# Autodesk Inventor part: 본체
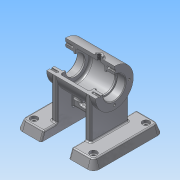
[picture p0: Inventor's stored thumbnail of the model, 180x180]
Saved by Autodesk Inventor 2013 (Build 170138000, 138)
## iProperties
Created: 2016-07
Part Number: 본체
Material: 알루미늄 6061
Document SubType Name: Modeling
Designer: Administrator
Density: 2.71 g/cm^3
Mass: 499.755 g
Surface Area: 541.889 cm^2
Volume: 184.411 cm^3
Author: Administrator
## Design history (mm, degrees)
sketch "스케치1"
  geometry: L1 (0, 0)-(0, 70); L2 (0, 70)-(70, 70); L3 (0, 87)-(0, 97); L4 (0, 97)-(70, 97); L5 (70, 97)-(70, 87); L6 (1, 86)-(11.7, 86); L7 (12, 85.7)-(12, 84); L8 (12, 84)-(14, 84); L9 (14, 84)-(14, 89); L10 (17, 92)-(53, 92); L11 (56, 89)-(56, 84); L12 (56, 84)-(58, 84); L13 (58, 84)-(58, 85.7); L14 (58.3, 86)-(69, 86); L15 (69, 86)-(70, 87); L16 (1, 86)-(0, 87); A1 r 0.3 centre (11.7, 85.7) between (12, 85.7) and (11.7, 86); A2 r 0.3 centre (58.3, 85.7) between (58.3, 86) and (58, 85.7); A3 r 3 centre (53, 89) between (56, 89) and (53, 92); A4 r 3 centre (17, 89) between (17, 92) and (14, 89); 7 further points
  constraints: 32 end point, 16 point on line, 8 point on circle, 8 tangent, 7 perpendicular, 6 parallel, 4 centre point, 2 equal radius, 1 vertical
  dimensions: "d0" = 70 distance of L1.start L1.end; "d1" = 70 distance of L1.end L2.end; "d2" = 54 diameter of L4 L2; "d3" = 12 distance of point (0, 86) point (12, 86); "d4" = 2 distance of L7.end L8.end; "d5" = 42 distance of point (14, 92) point (56, 92); "d6" = 2 distance of L11.end L12.end; "d7" = 32 diameter of L6 L2; "d8" = 28 diameter of L8 L2; "d9" = 44 diameter of L10 L2; "d10" = 28 diameter of L12 L2; "d11" = 32 diameter of L14 L2; "d12" = 0.3 radius of A1; "d13" = 3 radius of A3; "d14" = 1 distance of L14.end point (70, 86); "d15" = 1 distance of L5.end point (70, 86) (= d14); "d16" = 1 distance of L6.start point (0, 86) (= d14); "d17" = 1 distance of L3.start point (0, 86) (= d16)
revolve "회전1" sketch "스케치1" stored, may be unused: angle "d18" = 90 deg
node "작업 평면1"
sketch "스케치2"
  geometry: L1 (0, 27)-(0, -27) reference; L2 (0, 0)-(-22, 0); C1 r 5 at (-22, 0)
  constraints: 2 end point, 1 centre point, 1 coincident, 1 perpendicular
  dimensions: "d21" = 22 distance of L2.start L2.end; "d22" = 10 diameter of C1
extrude "돌출1" join sketch "스케치2" stored distance "d23" = 10; taper "d24" = 0 deg
sketch "스케치3"
  geometry: L1 (-90, 0)-(-90, -50); L2 (20, -50)-(20, 50); L3 (-90, 50)-(-90, 0); L4 (20, 50)-(-15, 50); L5 (-15, 50)-(-15, -50); L6 (20, -50)-(-15, -50); L7 (-90, -50)-(-55, -50); L8 (-55, -50)-(-55, 50); L9 (-55, 50)-(-90, 50); L10 (-55, 0)-(-15, 0); 1 further point
  constraints: 20 end point, 4 perpendicular, 2 equal length, 2 midpoint
  dimensions: "d27" = 50 distance of L1.start L1.end; "d29" = 100 distance of L2.start L2.end; "d31" = 35 distance of L2.end L4.end; "d33" = 35 distance of L1.end L7.end; "d34" = 100 distance of L7.end L8.end
extrude "돌출2" join sketch "스케치3" distance "d35" = 12; taper "d36" = 0 deg
sketch "스케치5"
  geometry: L1 (-15, 50)-(-15, -50) reference; L2 (-15, 0)-(-7, 0); L3 (-7, 0)-(-7, 27); L4 (-7, 27)-(-15, 27); L5 (-15, 27)-(-15, -27); L6 (-15, -27)-(-7, -27); L7 (-7, -27)-(-7, 27); 1 further point
  constraints: 12 end point, 3 perpendicular, 2 parallel, 1 horizontal, 1 midpoint, 1 point on line
  dimensions: "d41" = 8 distance of L2.start L2.end; "d42" = 27 distance of L2.end L3.end; "d43" = 54 distance of L6.end L3.end
extrude "돌출3" join sketch "스케치5" stored distance "d44" = 12; taper "d45" = 0 deg
node "작업 평면2"
sketch "스케치6"
  geometry: L1 (0, 0)-(6, 0); L2 (0, 0)-(25.441, -15.898); L3 (25.441, -15.898)-(22.262, -20.986); L4 (25.441, -15.898)-(21.133, -13.206); L5 (22.262, -20.986)-(19.145, -19.038); A1 r 27 centre (0, 0) between (19.145, -19.038) and (22.897, -14.308); 1 further point
  constraints: 10 end point, 2 point on circle, 2 point on line, 1 centre point, 1 coincident, 1 horizontal, 1 parallel, 1 perpendicular
  dimensions: "d48" = 30 distance of L1.start L2.end; "d49" = 32 deg angle of L1 L2
revolve "회전2" sketch "스케치6" stored, may be unused: angle "d52" = 90 deg
node "작업 평면3"
sketch "스케치7"
  geometry: 2 further points
  constraints: 1 other
feature "엠보싱1" sketch "스케치7" dims "d0" = 70, "d1" = 70, "d2" = 54, "d3" = 12, "d4" = 2, "d5" = 42, "d6" = 2, "d7" = 32, "d8" = 28, "d9" = 44, "d10" = 28, "d11" = 32, "d12" = 0.3, "d13" = 3, "d14" = 1, "d15" = 1 (= d14), "d16" = 1 (= d14), "d17" = 1 (= d16), "d54" = 0.5, "d55" = 0
sketch "스케치8"
  geometry: L1 (0, 43)-(70, 43) reference; L2 (55, 12)-(55, 70) reference; L3 (55, 43)-(55, 22); L4 (15, 12)-(15, 70) reference; L5 (55, 22)-(15, 22); L6 (15, 22)-(15, 43); L7 (15, 43)-(55, 43); 1 further point
  constraints: 8 end point, 5 point on line, 1 perpendicular
  dimensions: "d57" = 21 distance of L3.start L3.end; "d58" = 21 distance of L5.end L6.end
extrude "돌출4" join sketch "스케치8" stored distance "d59" = 8; taper "d60" = 0 deg
sketch "스케치9"
  geometry: L1 (-55, 0)-(-90, 0) reference; L2 (-35, -32)-(-23.5, -32); L3 (-23.5, -32)-(-23.5, -32); L4 (-27, -28.5)-(-43, -28.5); L5 (-46.5, -32)-(-46.5, -32); L6 (-43, -35.5)-(-27, -35.5); L7 (-23.5, -32)-(-23.5, -32); A1 r 3.5 centre (-43, -32) between (-43, -28.5) and (-46.5, -32); A2 r 3.5 centre (-43, -32) between (-46.5, -32) and (-43, -35.5); A3 r 3.5 centre (-27, -32) between (-27, -35.5) and (-23.5, -32); A4 r 3.5 centre (-27, -32) between (-23.5, -32) and (-27, -28.5); 5 further points
  constraints: 12 end point, 8 point on circle, 8 point on line, 8 tangent, 4 centre point, 3 equal radius, 3 perpendicular, 1 parallel
  dimensions: "d62" = 11.5 distance of L2.start L2.end; "d63" = 3.5 distance of L2.end point (-23.5, -28.5); "d64" = 23 distance of point (-23.5, -28.5) point (-46.5, -28.5); "d65" = 7 distance of point (-46.5, -28.5) point (-46.5, -35.5); "d66" = 23 distance of point (-46.5, -35.5) point (-23.5, -35.5); "d67" = 3.5 radius of A1
extrude "돌출5" cut sketch "스케치9" stored distance "d68" = 8; taper "d69" = 0 deg
feature "면 기울기1" dims angle "d70" = -20 deg
feature "면 기울기2" dims angle "d71" = 20 deg
feature "면 기울기3" dims angle "d72" = -20 deg
sketch "스케치10"
  geometry: C1 r 17 at (0, 0) reference; A1 r 21 centre (0, 0) between (0, 21) and (21, 0); 3 further points
  constraints: 4 point on circle, 1 centre point, 1 coincident
  dimensions: "d73" = 42 diameter of A1
hole "구멍1" sketch "스케치10" at (0, 21), (21, 0), (0, -21), (-21, 0) diameter "d74" = 3.242; stored, may be unused: countersink angle "d78" = 90 deg, drill point angle "d80" = 118 deg; dims "d75" = 8, "d76" = 4, "d77" = 2, "d79" = 10
sketch "스케치11"
  geometry: C1 r 5 at (0, 0) reference; 2 further points
  constraints: 1 coincident
hole "구멍2" sketch "스케치11" at (0, 0) diameter "d81" = 5.188; stored, may be unused: countersink angle "d85" = 90 deg, drill point angle "d87" = 118 deg; dims "d82" = 20, "d83" = 4, "d84" = 2, "d86" = 30
sketch "스케치12"
  geometry: C1 r 6 at (0, 0) reference; 2 further points
  constraints: 1 coincident
hole "구멍3" sketch "스케치12" at (0, 0) diameter "d88" = 5.188; stored, may be unused: countersink angle "d92" = 90 deg, drill point angle "d94" = 118 deg; dims "d89" = 20, "d90" = 4, "d91" = 2, "d93" = 30
sketch "스케치13"
  geometry: L1 (15.632, -45.632)-(15.632, 45.632) reference; L2 (15.632, 45.632)-(-15, 45.632) reference; L3 (20, -50)-(20, 50) reference; L4 (20, 50)-(-15, 50) reference; L5 (20, 50)-(7.5, 50); L6 (7.5, 50)-(7.5, 37.5); L7 (15.632, 0)-(6, 0); 3 further points
  constraints: 6 end point, 2 perpendicular, 1 coincident, 1 midpoint, 1 point on line, 1 symmetric about line
  dimensions: "d95" = 12.5 distance of L3.end L5.end; "d96" = 12.5 distance of L5.end L6.end
hole "구멍4" sketch "스케치13" at (7.5, 37.5), (7.5, -37.5) diameter "d97" = 6; stored, may be unused: countersink angle "d101" = 90 deg, drill point angle "d103" = 118 deg; dims "d98" = 20, "d99" = 10, "d100" = 4, "d102" = 30
fillet "모깎기1" dims "d104" = 10, "d105" = 5
fillet "모깎기2" dims "d106" = 10, "d107" = 5
fillet "모깎기3" dims "d108" = 10, "d109" = 5
fillet "모깎기4" dims "d110" = 10, "d111" = 5
sketch "스케치14"
  geometry: L1 (-40, 0)-(0, 0) reference; L2 (0, 4)-(0, 0) reference; L3 (-40, 4)-(0, 4) reference; L4 (-40, 0)-(-40, 4) reference; 1 further point
extrude "돌출6" join sketch "스케치14" stored distance "d112" = 8; taper "d113" = 0 deg
fillet "모깎기5" dims "d114" = 2
sketch "스케치15"
  geometry: L1 (40, 0)-(0, 0) reference; L2 (40, 4)-(40, 0) reference; L3 (0, 4)-(40, 4) reference; L4 (0, 0)-(0, 4) reference; 1 further point
extrude "돌출7" join sketch "스케치15" stored distance "d115" = 8; taper "d116" = 0 deg
fillet "모깎기6" dims "d117" = 2
fillet "모깎기7" dims "d118" = 2
fillet "모깎기8" dims "d119" = 2
fillet "모깎기9" dims "d120" = 2
fillet "모깎기10" dims "d121" = 2
fillet "모깎기11" dims "d122" = 2
sketch "스케치16"
  geometry: L1 (0, 0)-(57, 0); L2 (57, 0)-(57, -59); L3 (57, -59)-(0, -59); L4 (0, -59)-(0, 0); C1 r 27 at (0, 0) reference; 1 further point
  constraints: 8 end point, 2 parallel, 1 horizontal, 1 perpendicular
extrude "돌출8" cut sketch "스케치16" distance "d123" = 100; taper "d124" = 0 deg
node "솔리드1"
mirror "대칭1"
mirror "대칭2"
mirror "대칭3"
other parameters: "d46" = -35, "d53" = 27
